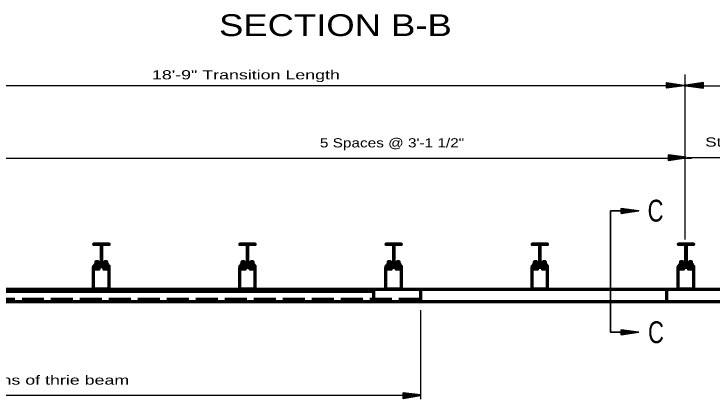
# Model space of a CAD drawing. Extents: x 856.9 to 891.7, y -2278.5 to -2254.7.
# Drawn here: x 868.03 to 877.8, y -2268.05 to -2262.66 of the extents above; entities that cross this region are included whole.
import ezdxf
from ezdxf.enums import TextEntityAlignment as Align

# ---------------------------------------------------------------- set-up
doc = ezdxf.new("R2010")
doc.units = 0
doc.header["$LTSCALE"] = 0.051
doc.linetypes.add('LONG_DASHED', pattern=[7.5, 6, -1.5])
doc.layers.add('1', color=7, linetype='Continuous', lineweight=70)

msp = doc.modelspace()

# ---------------------------------------------------------------- linework, layer by layer
at = {"layer": '1', "lineweight": 25}
for p, q in [((877.422, -2263.50467), (877.422, -2265.81658)), ((865.22225, -2263.65783), (877.422, -2263.65783)), ((877.422, -2263.66417), (881.52925, -2263.66417)), ((865.22225, -2264.67633), (877.5155, -2264.67633)), ((877.456, -2264.66783), (881.52925, -2264.66783)), ((873.72275, -2266.8045), (873.72275, -2268.05092)), ((865.22225, -2267.99842), (873.72275, -2267.99842))]:
    msp.add_line(p, q, dxfattribs=at)
at = {"layer": '1'}
for p, q in [((869.36083, -2266.51742), (869.36083, -2266.18658)), ((869.14267, -2266.51742), (869.14267, -2266.19725)), ((871.18942, -2266.51742), (871.18942, -2266.20767)), ((871.4075, -2266.51742), (871.4075, -2266.20767)), ((873.23617, -2266.51742), (873.23617, -2266.20767)), ((873.45425, -2266.50767), (873.45425, -2266.19725)), ((875.28283, -2266.50767), (875.28283, -2266.19725)), ((875.501, -2266.50767), (875.501, -2266.19725)), ((877.32958, -2266.50767), (877.32958, -2266.19725)), ((877.54783, -2266.50767), (877.54783, -2266.19725)), ((882.07667, -2266.51742), (865.61517, -2266.51742)), ((873.06783, -2266.545), (865.61842, -2266.545)), ((873.06783, -2266.68917), (873.06783, -2266.51742)), ((882.68767, -2266.68917), (866.22875, -2266.68917))]:
    msp.add_line(p, q, dxfattribs=at)
at = {"layer": '1', "linetype": 'LONG_DASHED'}
for p, q in [((873.72275, -2266.51817), (873.72275, -2266.68783)), ((877.16392, -2266.50767), (877.16392, -2266.69442)), ((873.72408, -2266.65825), (864.84167, -2266.65825))]:
    msp.add_line(p, q, dxfattribs=at)
at = {"layer": '1', "lineweight": 40}
for points in [[(877.4135, -2263.66), (877.16933, -2263.69133), (877.16933, -2263.62125)], [(877.435, -2263.66), (877.67917, -2263.69133), (877.67917, -2263.62125)], [(877.439, -2264.66783), (877.19483, -2264.6365), (877.19483, -2264.70658)], [(873.72275, -2267.99842), (873.4785, -2267.96708), (873.4785, -2268.03717)]]:
    msp.add_lwpolyline(points, close=True, dxfattribs=at)
for points in [[(877.16933, -2263.67367), (877.35275, -2263.66), (877.16933, -2263.639)], [(877.16933, -2263.66517), (877.25642, -2263.658), (877.16933, -2263.6475)], [(877.67917, -2263.67367), (877.49575, -2263.66), (877.67917, -2263.639)], [(877.67917, -2263.66517), (877.59208, -2263.658), (877.67917, -2263.6475)], [(877.19483, -2264.65417), (877.37825, -2264.66783), (877.19483, -2264.68883)], [(877.19483, -2264.66267), (877.28192, -2264.66983), (877.19483, -2264.68033)], [(873.4785, -2267.98475), (873.66175, -2267.99842), (873.4785, -2268.01942)], [(873.4785, -2267.99325), (873.56558, -2268.00042), (873.4785, -2268.01092)]]:
    msp.add_lwpolyline(points, dxfattribs=at)
at = {"layer": '1', "lineweight": 35}
for points in [[(876.38325, -2265.41217), (876.77617, -2265.41217), (876.532, -2265.38067), (876.532, -2265.45075), (876.77617, -2265.41217)], [(876.38325, -2265.41217), (876.38325, -2267.115), (876.77617, -2267.115)], [(876.532, -2265.39833), (876.71533, -2265.41217), (876.532, -2265.43308)], [(876.532, -2265.39833), (876.71533, -2265.41217), (876.532, -2265.43308)], [(876.532, -2265.40683), (876.61908, -2265.414), (876.532, -2265.42458)], [(876.532, -2265.40683), (876.61908, -2265.414), (876.532, -2265.42458)], [(876.532, -2267.10125), (876.71533, -2267.115), (876.532, -2267.136)], [(876.532, -2267.10125), (876.71533, -2267.115), (876.532, -2267.136)], [(876.532, -2267.10975), (876.61908, -2267.11692), (876.532, -2267.12742)], [(876.532, -2267.10975), (876.61908, -2267.11692), (876.532, -2267.12742)]]:
    msp.add_lwpolyline(points, dxfattribs=at)
for points in [[(876.77617, -2265.41217), (876.532, -2265.38067), (876.532, -2265.45075)], [(876.77617, -2267.115), (876.532, -2267.08367), (876.532, -2267.15367)], [(876.77617, -2267.115), (876.532, -2267.08367), (876.532, -2267.15367)]]:
    msp.add_lwpolyline(points, close=True, dxfattribs=at)
at = {"layer": '1', "lineweight": 60}
for points in [[(869.14267, -2266.19725), (869.36083, -2266.19725), (869.36083, -2266.18658), (869.25667, -2266.18658), (869.25667, -2265.88675), (869.36083, -2265.88675), (869.36083, -2265.877), (869.14267, -2265.877), (869.14267, -2265.88675), (869.24675, -2265.88675), (869.24675, -2266.18658), (869.14267, -2266.18658)], [(871.18942, -2266.19725), (871.4075, -2266.19725), (871.4075, -2266.18658), (871.30342, -2266.18658), (871.30342, -2265.88675), (871.4075, -2265.88675), (871.4075, -2265.877), (871.18942, -2265.877), (871.18942, -2265.88675), (871.2935, -2265.88675), (871.2935, -2266.18658), (871.18942, -2266.18658)], [(873.23617, -2266.19725), (873.45425, -2266.19725), (873.45425, -2266.18658), (873.35008, -2266.18658), (873.35008, -2265.88675), (873.45425, -2265.88675), (873.45425, -2265.877), (873.23617, -2265.877), (873.23617, -2265.88675), (873.34033, -2265.88675), (873.34033, -2266.18658), (873.23617, -2266.18658)], [(875.28283, -2266.19725), (875.501, -2266.19725), (875.501, -2266.18658), (875.39692, -2266.18658), (875.39692, -2265.88675), (875.501, -2265.88675), (875.501, -2265.877), (875.28283, -2265.877), (875.28283, -2265.88675), (875.38717, -2265.88675), (875.38717, -2266.18658), (875.28283, -2266.18658)], [(877.32958, -2266.19725), (877.54783, -2266.19725), (877.54783, -2266.18658), (877.4435, -2266.18658), (877.4435, -2265.88675), (877.54783, -2265.88675), (877.54783, -2265.877), (877.32958, -2265.877), (877.32958, -2265.88675), (877.43375, -2265.88675), (877.43375, -2266.18658), (877.32958, -2266.18658)], [(877.43375, -2266.20767), (877.54783, -2266.20767), (877.54783, -2266.19725), (877.32958, -2266.19725), (877.32958, -2266.20767)]]:
    msp.add_lwpolyline(points, close=True, dxfattribs=at)
for points in [[(869.16092, -2266.18658), (869.16092, -2266.16183), (869.21933, -2266.16183), (869.21933, -2266.18658)], [(869.1735, -2266.16183), (869.1735, -2266.12583), (869.20758, -2266.12583), (869.20758, -2266.16183)], [(869.34233, -2266.18658), (869.34233, -2266.16183), (869.28425, -2266.16183), (869.28425, -2266.18658)], [(869.33008, -2266.16183), (869.33008, -2266.12583), (869.296, -2266.12583), (869.296, -2266.16183)], [(871.20775, -2266.18658), (871.20775, -2266.16183), (871.26608, -2266.16183), (871.26608, -2266.18658)], [(871.22025, -2266.16183), (871.22025, -2266.12583), (871.25433, -2266.12583), (871.25433, -2266.16183)], [(871.38917, -2266.18658), (871.38917, -2266.16183), (871.33092, -2266.16183), (871.33092, -2266.18658)], [(871.37692, -2266.16183), (871.37692, -2266.12583), (871.34258, -2266.12583), (871.34258, -2266.16183)], [(873.2545, -2266.18658), (873.2545, -2266.16183), (873.31275, -2266.16183), (873.31275, -2266.18658)], [(873.26692, -2266.16183), (873.26692, -2266.12583), (873.301, -2266.12583), (873.301, -2266.16183)], [(873.43592, -2266.18658), (873.43592, -2266.16183), (873.37758, -2266.16183), (873.37758, -2266.18658)], [(873.42342, -2266.16183), (873.42342, -2266.12583), (873.38942, -2266.12583), (873.38942, -2266.16183)], [(875.30133, -2266.18658), (875.30133, -2266.16183), (875.35967, -2266.16183), (875.35967, -2266.18658)], [(875.31358, -2266.16183), (875.31358, -2266.12583), (875.34783, -2266.12583), (875.34783, -2266.16183)], [(875.48267, -2266.18658), (875.48267, -2266.16183), (875.42433, -2266.16183), (875.42433, -2266.18658)], [(875.47017, -2266.16183), (875.47017, -2266.12583), (875.43617, -2266.12583), (875.43617, -2266.16183)], [(877.34808, -2266.18658), (877.34808, -2266.16183), (877.40617, -2266.16183), (877.40617, -2266.18658)], [(877.36033, -2266.16183), (877.36033, -2266.12583), (877.3945, -2266.12583), (877.3945, -2266.16183)], [(877.5295, -2266.18658), (877.5295, -2266.16183), (877.47108, -2266.16183), (877.47108, -2266.18658)], [(877.517, -2266.16183), (877.517, -2266.12583), (877.48283, -2266.12583), (877.48283, -2266.16183)], [(869.16092, -2266.19725), (869.16092, -2266.23267), (869.21933, -2266.23267), (869.21933, -2266.19725)], [(869.34233, -2266.19725), (869.34233, -2266.23267), (869.28425, -2266.23267), (869.28425, -2266.19725)], [(871.2935, -2266.20767), (871.4075, -2266.20767), (871.4075, -2266.19725), (871.18942, -2266.19725), (871.18942, -2266.20767), (871.2935, -2266.20767), (871.2935, -2266.20908)], [(871.20775, -2266.20767), (871.20775, -2266.23267), (871.26608, -2266.23267), (871.26608, -2266.20767)], [(871.38917, -2266.20767), (871.38917, -2266.23267), (871.33092, -2266.23267), (871.33092, -2266.20767)], [(873.35008, -2266.20775), (873.35008, -2266.20767), (873.45425, -2266.20767), (873.45425, -2266.19725), (873.23617, -2266.19725), (873.23617, -2266.20767), (873.35008, -2266.20767)], [(873.2545, -2266.20767), (873.2545, -2266.23267), (873.31275, -2266.23267), (873.31275, -2266.20767)], [(873.43592, -2266.20767), (873.43592, -2266.23267), (873.37758, -2266.23267), (873.37758, -2266.20767)], [(875.39692, -2266.20783), (875.39692, -2266.20767), (875.501, -2266.20767), (875.501, -2266.19725), (875.28283, -2266.19725), (875.28283, -2266.20767), (875.39692, -2266.20767)], [(875.30133, -2266.20767), (875.30133, -2266.23267), (875.35967, -2266.23267), (875.35967, -2266.20767)], [(875.48267, -2266.20767), (875.48267, -2266.23267), (875.42433, -2266.23267), (875.42433, -2266.20767)], [(877.34808, -2266.20767), (877.34808, -2266.23267), (877.40617, -2266.23267), (877.40617, -2266.20767)], [(877.5295, -2266.20767), (877.5295, -2266.23267), (877.47108, -2266.23267), (877.47108, -2266.20767)], [(869.24675, -2266.50767), (869.14267, -2266.50767), (869.14267, -2266.51742)], [(869.14267, -2266.51742), (869.36083, -2266.51742), (869.36083, -2266.50767), (869.24675, -2266.50767)], [(871.30342, -2266.50767), (871.18942, -2266.50767), (871.18942, -2266.51742)], [(871.18942, -2266.51742), (871.4075, -2266.51742), (871.4075, -2266.50767), (871.30342, -2266.50767)], [(873.35008, -2266.50767), (873.23617, -2266.50767), (873.23617, -2266.51742)], [(873.23617, -2266.51742), (873.45425, -2266.51742), (873.45425, -2266.50767), (873.35008, -2266.50767)], [(875.39692, -2266.50767), (875.28283, -2266.50767), (875.28283, -2266.51742)], [(875.28283, -2266.51742), (875.501, -2266.51742), (875.501, -2266.50767), (875.39692, -2266.50767)], [(877.4435, -2266.50767), (877.32958, -2266.50767), (877.32958, -2266.51742)], [(877.32958, -2266.51742), (877.54783, -2266.51742), (877.54783, -2266.50767), (877.4435, -2266.50767)]]:
    msp.add_lwpolyline(points, dxfattribs=at)

# ---------------------------------------------------------------- texts
at = {"layer": '1', "width": 1.25}
msp.add_text('SECTION B-B', height=0.3052, dxfattribs=at).set_placement((872.52896, -2262.96608), align=Align.CENTER)
at = {"layer": '1'}
for s, height, width, p in [('18\'-9" Transition Length', 0.1286, 1.45, (869.96025, -2263.57275)), ('5 Spaces @ 3\'-1 1/2"', 0.1286, 1.25, (872.3115, -2264.52583)), ('Standard guardrail', 0.1286, 1.4, (877.70725, -2264.51483)), ('C', 0.3059, 0.75, (876.90117, -2265.56483)), ('C', 0.3059, 0.75, (876.90717, -2267.26767)), ('Two sections of thrie beam', 0.1286, 1.45, (866.6615, -2267.84917))]:
    msp.add_text(s, height=height, dxfattribs=dict(at, width=width)).set_placement(p)

doc.saveas('drawing.dxf')
